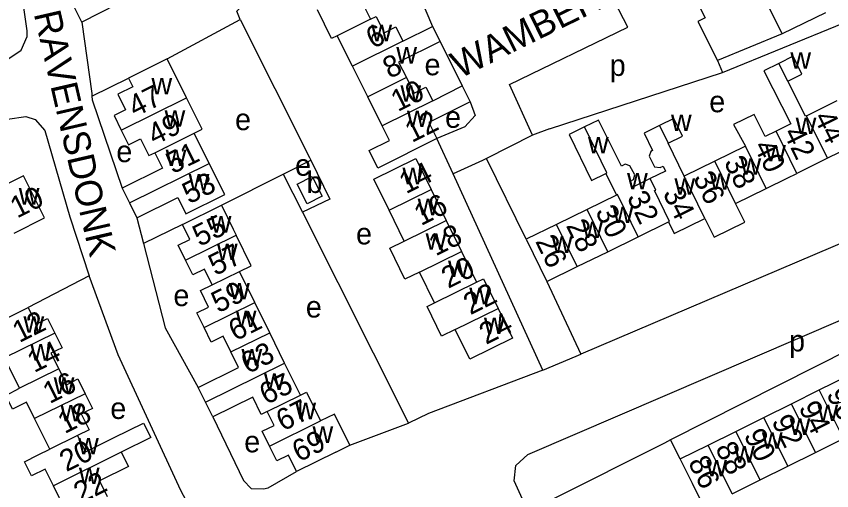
# Model space of a CAD drawing. Extents: x 157794 to 159375, y 380877 to 382306.
# Drawn here: x 158356.3 to 158508.3, y 381547.1 to 381635.5 of the extents above; entities that cross this region are included whole.
import ezdxf

# ---------------------------------------------------------------- set-up
doc = ezdxf.new("R2010")
doc.units = 0
for name, color, linetype in [('BLT_Basislijn', 7, 'Continuous'), ('BLT_Bebouwing', 7, 'Continuous'), ('BLT_Centroide', 7, 'Continuous'), ('BLT_Huisnummer', 7, 'Continuous'), ('BLT_Huisnummer_ tussenligend', 7, 'Continuous'), ('BLT_Onderverdeling_panden', 7, 'Continuous'), ('BLT_Straatnaam', 7, 'Continuous')]:
    doc.layers.add(name, color=color, linetype=linetype)

msp = doc.modelspace()

# ---------------------------------------------------------------- linework, layer by layer
at = {"layer": 'BLT_Basislijn'}
for p, q in [((158426.31, 381651.29), (158433.86, 381633.66)), ((158384.42, 381627.62), (158397.98, 381634.93)), ((158499.08, 381632.26), (158486.99, 381627.33)), ((158435.27, 381630.84), (158439.41, 381622.56)), ((158486.99, 381627.33), (158487.96, 381625.08)), ((158370.34, 381620.66), (158377.17, 381624.03)), ((158455.71, 381614.58), (158487.96, 381625.08)), ((158452.51, 381613.42), (158443.96, 381609.03)), ((158437.69, 381606.18), (158434.68, 381612.75)), ((158406.01, 381606.12), (158411.16, 381608.72)), ((158451.34, 381593.99), (158443.96, 381609.03)), ((158394.51, 381600.34), (158406.01, 381606.12)), ((158406.01, 381606.12), (158409.65, 381599.06)), ((158454.42, 381569.6), (158437.69, 381606.18)), ((158531.99, 381602.59), (158461.52, 381572.61)), ((158378.74, 381598), (158379.99, 381593.18)), ((158409.65, 381599.06), (158429.41, 381559.71)), ((158387.23, 381596.75), (158379.99, 381593.18)), ((158369.82, 381587.16), (158358.45, 381581.26)), ((158455.19, 381586.12), (158461.52, 381572.61)), ((158529.73, 381582.61), (158478.22, 381556.59)), ((158418.46, 381555.63), (158429.41, 381559.71)), ((158480.07, 381553.05), (158478.22, 381556.59))]:
    msp.add_line(p, q, dxfattribs=at)
for points in [[(158333.92, 381618.28), (158353.73, 381626.96), (158357.15, 381629.2), (158358.3, 381631.79), (158358.3, 381632.82), (158354.9, 381656.82)], [(158481.25, 381649.01), (158482.33, 381646.83), (158480.93, 381646.13), (158483.51, 381640.93), (158482.18, 381640.27), (158484.68, 381635.23), (158483.32, 381634.56), (158486.99, 381627.33)], [(158397.98, 381634.93), (158397.4, 381636.52), (158398.36, 381637.43), (158409.44, 381642.68)], [(158452.51, 381613.42), (158448.19, 381622.81), (158470.26, 381633.5), (158466.15, 381641.57)], [(158368.49, 381634.45), (158370.32, 381621.16), (158370.34, 381620.66)], [(158397.98, 381634.93), (158410.91, 381609.24), (158411.16, 381608.72)], [(158487.96, 381625.08), (158510.46, 381634.29), (158511.64, 381634.27), (158512.56, 381632.75), (158513.27, 381633.06), (158513.86, 381632.9), (158516.19, 381633.99)], [(158370.34, 381620.66), (158370.38, 381619.96), (158376.01, 381603.52)], [(158440.89, 381619.61), (158441.82, 381617.04), (158439.9, 381614.93), (158434.68, 381612.75)], [(158318.57, 381599.87), (158354.61, 381616.4), (158358.01, 381616.87), (158359.79, 381616.31), (158361.61, 381614.24), (158366.23, 381598.17), (158369.82, 381587.16)], [(158455.71, 381614.58), (158452.51, 381613.42)], [(158411.16, 381608.72), (158414.72, 381601.49), (158409.65, 381599.06)], [(158443.96, 381609.03), (158443.2, 381608.64), (158437.69, 381606.18)], [(158451.81, 381542.95), (158449.11, 381549.01), (158449.43, 381551.81), (158451.61, 381553.86), (158561.13, 381600.93)], [(158379.99, 381593.18), (158384.04, 381577.49), (158390.19, 381566.38)], [(158379.01, 381534.43), (158389.61, 381538.83), (158389.96, 381539.81), (158389.99, 381541.44), (158386.97, 381547.16), (158375.23, 381572.49), (158369.82, 381587.16)], [(158454.42, 381569.6), (158460.65, 381572.24), (158461.52, 381572.61)], [(158454.42, 381569.6), (158433.11, 381561.51), (158429.41, 381559.71)], [(158392.88, 381560.91), (158398.61, 381549.07), (158400.04, 381547.56), (158402.33, 381547.52), (158403.23, 381547.68), (158408.5, 381550.73)], [(158478.22, 381556.59), (158477.09, 381556.02), (158455.91, 381545.38), (158451.81, 381542.95)]]:
    msp.add_lwpolyline(points, dxfattribs=at)
at = {"layer": 'BLT_Bebouwing'}
for p, q in [((158368.49, 381634.45), (158367.11, 381637.2)), ((158507.17, 381636.16), (158499.08, 381632.26)), ((158428.36, 381630.92), (158433.86, 381633.66)), ((158433.86, 381633.66), (158435.27, 381630.84)), ((158418.94, 381626.23), (158416.1, 381631.92)), ((158384.42, 381627.62), (158377.17, 381624.03)), ((158388.02, 381620.36), (158384.42, 381627.62)), ((158421.78, 381620.53), (158418.94, 381626.23)), ((158433.9, 381619.81), (158439.41, 381622.56)), ((158439.41, 381622.56), (158440.89, 381619.61)), ((158424.48, 381615.12), (158421.78, 381620.53)), ((158503.6, 381617.01), (158509.3, 381619.82)), ((158392.25, 381608.12), (158389.45, 381613.78)), ((158513.2, 381611.88), (158507.49, 381609.08)), ((158492.21, 381611.35), (158486.49, 381608.55)), ((158507.49, 381609.08), (158501.78, 381606.27)), ((158486.49, 381608.55), (158480.78, 381605.74)), ((158376.01, 381603.52), (158377.38, 381600.76)), ((158433.61, 381603.27), (158436.44, 381597.5)), ((158490.35, 381600.67), (158496.07, 381603.47)), ((158468.16, 381602.23), (158462.68, 381599.54)), ((158377.38, 381600.76), (158378.74, 381598)), ((158387.23, 381596.75), (158394.51, 381600.34)), ((158462.68, 381599.54), (158457.01, 381596.76)), ((158428.6, 381593.66), (158425.77, 381599.43)), ((158436.44, 381597.5), (158439.26, 381591.74)), ((158457.01, 381596.76), (158451.34, 381593.99)), ((158472.2, 381594.46), (158477.87, 381597.23)), ((158451.34, 381593.99), (158455.19, 381586.12)), ((158466.53, 381591.68), (158472.2, 381594.46)), ((158439.26, 381591.74), (158442.09, 381585.97)), ((158460.86, 381588.9), (158466.53, 381591.68)), ((158455.19, 381586.12), (158460.86, 381588.9)), ((158400.73, 381582.23), (158397.89, 381588)), ((158434.25, 381582.12), (158431.42, 381587.89)), ((158351.23, 381577.69), (158358.45, 381581.26)), ((158403.52, 381576.58), (158400.73, 381582.23)), ((158406.3, 381570.92), (158403.52, 381576.58)), ((158356.89, 381566.23), (158354.09, 381571.89)), ((158409.24, 381564.96), (158406.3, 381570.92)), ((158505.98, 381565.92), (158511.16, 381568.5)), ((158391.53, 381563.65), (158390.19, 381566.38)), ((158500.8, 381563.35), (158505.98, 381565.92)), ((158392.88, 381560.91), (158391.53, 381563.65)), ((158495.62, 381560.77), (158500.8, 381563.35)), ((158362.49, 381554.87), (158359.68, 381560.57)), ((158490.43, 381558.2), (158495.62, 381560.77)), ((158485.25, 381555.62), (158490.43, 381558.2)), ((158505.3, 381554.29), (158510.48, 381556.87)), ((158480.07, 381553.05), (158485.25, 381555.62)), ((158415.86, 381554.35), (158408.5, 381550.73)), ((158500.11, 381551.72), (158505.3, 381554.29)), ((158494.93, 381549.15), (158500.11, 381551.72)), ((158365.95, 381542.44), (158363.17, 381548.08)), ((158489.75, 381546.57), (158494.93, 381549.15))]:
    msp.add_line(p, q, dxfattribs=at)
for points in [[(158380.39, 381643.8), (158373.74, 381640.47), (158375.1, 381637.77), (158368.49, 381634.45)], [(158421.9, 381641.47), (158423.25, 381638.75), (158421, 381637.63), (158422.3, 381635.01)], [(158499.08, 381632.26), (158495.45, 381639.6), (158495.1, 381640.29), (158497.92, 381641.82)], [(158416.1, 381631.92), (158415.06, 381631.4), (158412.4, 381636.74)], [(158422.3, 381635.01), (158423.33, 381635.52), (158424.86, 381632.46), (158427.04, 381633.55), (158428.36, 381630.92)], [(158435.27, 381630.84), (158427.55, 381627.01), (158428.99, 381624.13)], [(158500.11, 381623.43), (158502.74, 381624.76), (158501.11, 381628.09), (158498.44, 381626.75)], [(158498.44, 381626.75), (158495.65, 381625.36), (158500.7, 381615.5)], [(158377.17, 381624.03), (158377.97, 381622.41), (158375.18, 381621.03), (158376.62, 381618.14), (158374.48, 381617.08), (158375.84, 381614.33)], [(158428.99, 381624.13), (158430.43, 381621.24), (158432.63, 381622.34), (158433.9, 381619.81)], [(158503.6, 381617.01), (158503.39, 381616.91), (158500.11, 381623.43)], [(158389.45, 381613.78), (158390.92, 381614.51), (158388.02, 381620.36)], [(158440.89, 381619.61), (158433.17, 381615.78), (158434.68, 381612.75)], [(158474.42, 381605.3), (158471.19, 381603.71), (158470.66, 381604.74), (158471.33, 381605.1), (158471.57, 381605.98), (158470.66, 381607.7), (158469.78, 381608.01), (158469.08, 381607.64), (158464.83, 381616.21), (158462.22, 381614.93)], [(158477.81, 381611.89), (158480.45, 381613.18), (158478.84, 381616.47), (158476.2, 381615.17)], [(158493.86, 381617.25), (158490.01, 381615.35), (158492.21, 381611.35)], [(158497.92, 381614.14), (158495.87, 381613.17), (158493.86, 381617.25)], [(158434.68, 381612.75), (158423.68, 381607.26), (158422.06, 381610.53), (158425.83, 381612.41), (158424.48, 381615.12)], [(158462.22, 381614.93), (158459.34, 381613.52), (158463.54, 381604.94), (158466.2, 381606.24)], [(158476.2, 381615.17), (158473.3, 381613.75), (158474.88, 381610.53), (158474.55, 381610.37), (158474.28, 381609.48), (158475.25, 381607.49), (158476.31, 381607.36), (158476.86, 381607.63), (158477.31, 381606.71), (158474.42, 381605.3)], [(158500.7, 381615.5), (158497.92, 381614.14)], [(158375.84, 381614.33), (158377.2, 381611.58), (158379.43, 381612.69), (158380.97, 381609.58), (158382.07, 381610.12)], [(158480.78, 381605.74), (158477.81, 381611.89)], [(158382.07, 381610.12), (158383.5, 381607.23), (158376.01, 381603.52)], [(158425.77, 381599.43), (158422.94, 381605.2), (158430.78, 381609.04), (158433.61, 381603.27)], [(158378.74, 381598), (158386.37, 381601.78), (158387.88, 381598.72), (158395.13, 381602.31), (158392.25, 381608.12)], [(158355.87, 381595.11), (158361.54, 381597.96), (158357.58, 381605.84), (158351.91, 381602.99)], [(158466.2, 381606.24), (158468.16, 381602.23)], [(158496.07, 381603.47), (158500, 381605.4), (158501.78, 381606.27)], [(158394.51, 381600.34), (158396.72, 381595.85), (158397.25, 381594.78)], [(158484.64, 381597.88), (158486.39, 381594.36), (158492.07, 381597.15), (158490.35, 381600.67)], [(158387.81, 381590.13), (158386.45, 381592.9), (158388.61, 381593.96), (158387.23, 381596.75)], [(158477.87, 381597.23), (158478.93, 381595.08), (158484.64, 381597.88)], [(158397.89, 381588), (158400.06, 381589.07), (158397.25, 381594.78)], [(158431.42, 381587.89), (158428.73, 381586.57), (158425.9, 381592.34), (158428.6, 381593.66)], [(158392.78, 381585.49), (158391.33, 381588.43), (158389.17, 381587.37), (158387.81, 381590.13)], [(158442.09, 381585.97), (158443.38, 381586.6), (158446.09, 381581.08)], [(158391.27, 381577.57), (158389.93, 381580.3), (158392.11, 381581.37), (158390.61, 381584.42), (158392.78, 381585.49)], [(158358.45, 381581.26), (158359.96, 381578.19), (158362.1, 381579.25), (158363.46, 381576.51)], [(158438.1, 381577.16), (158435.57, 381575.91), (158432.86, 381581.44), (158434.25, 381582.12)], [(158446.09, 381581.08), (158448.8, 381575.55), (158440.8, 381571.64), (158438.1, 381577.16)], [(158396.25, 381573), (158394.81, 381575.92), (158392.61, 381574.84), (158391.27, 381577.57)], [(158363.46, 381576.51), (158364.81, 381573.77), (158362.73, 381572.74), (158364.17, 381569.82)], [(158390.19, 381566.38), (158397.69, 381570.07), (158396.25, 381573)], [(158364.17, 381569.82), (158365.61, 381566.9), (158367.76, 381567.97), (158369.11, 381565.22)], [(158359.68, 381560.57), (158358.17, 381563.63), (158355.56, 381562.32), (158354.3, 381564.88), (158356.89, 381566.23)], [(158369.11, 381565.22), (158370.47, 381562.48), (158368.37, 381561.44), (158369.83, 381558.49), (158367.65, 381557.42)], [(158403.03, 381561.9), (158401.93, 381561.36), (158400.34, 381564.58), (158392.88, 381560.91)], [(158409.24, 381564.96), (158410.36, 381565.51), (158413.01, 381560.14)], [(158403.48, 381555.45), (158402.12, 381558.21), (158404.32, 381559.29), (158403.03, 381561.9)], [(158418.46, 381555.63), (158415.61, 381561.42), (158413.01, 381560.14)], [(158374.51, 381557.05), (158380, 381559.75), (158381.33, 381557.05), (158375.84, 381554.34)], [(158367.65, 381557.42), (158369.14, 381554.4), (158374.51, 381557.05)], [(158408.5, 381550.73), (158407.01, 381553.75), (158404.84, 381552.68), (158403.48, 381555.45)], [(158415.86, 381554.35), (158418.46, 381555.63)], [(158363.17, 381548.08), (158361.65, 381551.17), (158359.1, 381549.91), (158357.79, 381552.55), (158360.34, 381553.81), (158362.49, 381554.87)], [(158375.84, 381554.34), (158377.18, 381551.63), (158371.78, 381548.96), (158373.23, 381546.04)], [(158484.57, 381543.99), (158484.04, 381545.06), (158482.33, 381548.5), (158480.07, 381553.05)]]:
    msp.add_lwpolyline(points, dxfattribs=at)
msp.add_lwpolyline([(158408.65, 381604.28), (158411.44, 381605.67), (158413.27, 381602), (158410.47, 381600.61)], close=True, dxfattribs=at)
at = {"layer": 'BLT_Onderverdeling_panden'}
for p, q in [((158422.3, 381635.01), (158416.1, 381631.92)), ((158428.36, 381630.92), (158418.94, 381626.23)), ((158500.11, 381623.43), (158498.44, 381626.75)), ((158428.99, 381624.13), (158421.78, 381620.53)), ((158375.84, 381614.33), (158388.02, 381620.36)), ((158433.9, 381619.81), (158424.48, 381615.12)), ((158507.49, 381609.08), (158503.6, 381617.01)), ((158476.2, 381615.17), (158477.81, 381611.89)), ((158382.07, 381610.12), (158389.45, 381613.78)), ((158501.78, 381606.27), (158497.92, 381614.14)), ((158496.07, 381603.47), (158492.21, 381611.35)), ((158377.38, 381600.76), (158392.25, 381608.12)), ((158490.35, 381600.67), (158486.49, 381608.55)), ((158484.64, 381597.88), (158480.78, 381605.74)), ((158425.77, 381599.43), (158433.61, 381603.27)), ((158466.53, 381591.68), (158462.68, 381599.54)), ((158428.6, 381593.66), (158436.44, 381597.5)), ((158460.86, 381588.9), (158457.01, 381596.76)), ((158387.81, 381590.13), (158397.25, 381594.78)), ((158431.42, 381587.89), (158439.26, 381591.74)), ((158392.78, 381585.49), (158397.89, 381588)), ((158434.25, 381582.12), (158442.09, 381585.97)), ((158391.27, 381577.57), (158400.73, 381582.23)), ((158438.1, 381577.16), (158446.09, 381581.08)), ((158363.46, 381576.51), (158354.09, 381571.89)), ((158396.25, 381573), (158403.52, 381576.58)), ((158391.53, 381563.65), (158406.3, 381570.92)), ((158364.17, 381569.82), (158356.89, 381566.23)), ((158369.11, 381565.22), (158359.68, 381560.57)), ((158403.03, 381561.9), (158409.24, 381564.96)), ((158510.48, 381556.87), (158505.98, 381565.92)), ((158505.3, 381554.29), (158500.8, 381563.35)), ((158403.48, 381555.45), (158413.01, 381560.14)), ((158500.11, 381551.72), (158495.62, 381560.77)), ((158367.65, 381557.42), (158362.49, 381554.87)), ((158494.93, 381549.15), (158490.43, 381558.2)), ((158489.75, 381546.57), (158485.25, 381555.62)), ((158375.84, 381554.34), (158363.17, 381548.08))]:
    msp.add_line(p, q, dxfattribs=at)
for points in [[(158466.2, 381606.24), (158466.37, 381606.4), (158462.22, 381614.93)], [(158477.87, 381597.23), (158478.07, 381597.33), (158475.28, 381603.05), (158475.48, 381603.15), (158474.42, 381605.3)], [(158472.2, 381594.46), (158468.35, 381602.32), (158468.16, 381602.23)]]:
    msp.add_lwpolyline(points, dxfattribs=at)

# ---------------------------------------------------------------- texts
at = {"layer": 'BLT_Centroide'}
for s, p in [('w', (158422.45, 381630.88)), ('w', (158427.11, 381626.73)), ('w', (158500.59, 381625.77)), ('e', (158432.38, 381624.55)), ('p', (158466.91, 381624.43)), ('w', (158381.46, 381620.97)), ('w', (158427.88, 381619.62)), ('e', (158485.46, 381617.66)), ('w', (158383.91, 381614.97)), ('w', (158429.09, 381614.91)), ('e', (158436.21, 381614.76)), ('e', (158397.05, 381614.33)), ('w', (158478.33, 381614.17)), ('w', (158501.58, 381613.61)), ('w', (158462.86, 381609.98)), ('e', (158374.92, 381608.37)), ('w', (158384.12, 381607.62)), ('w', (158495.89, 381608.5)), ('e', (158408.24, 381605.83)), ('w', (158491.28, 381606)), ('w', (158428.27, 381604.25)), ('w', (158388.39, 381603.06)), ('b', (158410.38, 381602.62)), ('w', (158470.14, 381603.27)), ('w', (158485.56, 381603.22)), ('w', (158478.97, 381602.3)), ('w', (158356.72, 381600.47)), ('w', (158431.1, 381598.47)), ('w', (158467.44, 381597)), ('w', (158392.51, 381595.25)), ('w', (158461.77, 381594.22)), ('e', (158419.61, 381593.04)), ('w', (158432.58, 381592.03)), ('w', (158456.09, 381591.44)), ('w', (158393.67, 381590.12)), ('w', (158436.76, 381586.94)), ('w', (158395.93, 381582.78)), ('e', (158385.56, 381581.54)), ('w', (158440.73, 381581.88)), ('e', (158410.25, 381579.41)), ('w', (158397.18, 381577.62)), ('w', (158357.6, 381576.56)), ('w', (158443.45, 381576.34)), ('p', (158500.35, 381573.09)), ('w', (158358.88, 381571.38)), ('w', (158398.25, 381570.45)), ('w', (158363.23, 381565.19)), ('w', (158402.45, 381565.91)), ('w', (158364.5, 381560.06)), ('e', (158373.79, 381560.51)), ('w', (158408.29, 381560.47)), ('w', (158505.64, 381560.11)), ('w', (158500.45, 381557.53)), ('w', (158411.49, 381556.06)), ('w', (158367.78, 381553.91)), ('e', (158398.76, 381554.29)), ('w', (158495.28, 381554.95)), ('w', (158490.09, 381552.39)), ('w', (158484.91, 381549.8)), ('w', (158367.93, 381548.38))]:
    msp.add_text(s, height=4, dxfattribs=at).set_placement(p)
at = {"layer": 'BLT_Huisnummer'}
for s, rotation, p in [('6', 26.4946, (158422.74, 381629.42)), ('47', 26.3463, (158378.4, 381616.68)), ('10', 26.4946, (158427.39, 381617.68)), ('42', 296.0997, (158499.2, 381613.83)), ('51', 26.3463, (158385.43, 381606.1)), ('38', 296.0997, (158488.13, 381608.36)), ('14', 26.4946, (158428.92, 381602.37)), ('10', 26.6706, (158356.42, 381597.83)), ('34', 296.0997, (158476.73, 381602.58)), ('30', 296.0997, (158464.14, 381599.18)), ('55', 26.3463, (158390.41, 381592.55)), ('18', 26.4946, (158434.44, 381590.79)), ('26', 296.0997, (158452.96, 381593.63)), ('59', 26.3463, (158393.9, 381580.17)), ('12', 26.2747, (158356.81, 381574.64)), ('24', 26.4946, (158443.85, 381574.3)), ('63', 26.3463, (158399.42, 381568.83)), ('16', 26.2747, (158362.48, 381563.27)), ('94', 296.418, (158502.06, 381562.65)), ('90', 296.418, (158491.84, 381557.49)), ('69', 26.3463, (158408.96, 381552.41)), ('20', 26.2747, (158365.58, 381550.58)), ('86', 296.418, (158481.45, 381552.44))]:
    msp.add_text(s, height=4, rotation=rotation, dxfattribs=at).set_placement(p)
at = {"layer": 'BLT_Huisnummer_ tussenligend'}
for s, rotation, p in [('8', 26.4946, (158425.87, 381623.84)), ('12', 26.4946, (158430.03, 381611.94)), ('49', 26.3463, (158382.02, 381611.43)), ('44', 296.0997, (158504.87, 381616.74)), ('40', 296.0997, (158493.67, 381611.37)), ('53', 26.3463, (158388.48, 381600.48)), ('36', 296.0997, (158482.38, 381605.48)), ('16', 26.4946, (158431.72, 381596.45)), ('32', 296.0997, (158470.03, 381601.81)), ('28', 296.0997, (158458.7, 381596.55)), ('57', 26.3463, (158393.36, 381587.12)), ('20', 26.4946, (158436.8, 381584.74)), ('22', 26.4946, (158440.92, 381579.82)), ('61', 26.3463, (158397.1, 381574.95)), ('14', 26.2747, (158359.59, 381569.05)), ('65', 26.3463, (158402.86, 381563.08)), ('96', 296.418, (158507.23, 381565.18)), ('18', 26.2747, (158365.27, 381557.68)), ('67', 26.3463, (158405.97, 381558.15)), ('92', 296.418, (158497.01, 381560.12)), ('88', 296.418, (158486.51, 381555.07)), ('22', 26.2747, (158368.22, 381544.67))]:
    msp.add_text(s, height=4, rotation=rotation, dxfattribs=at).set_placement(p)
at = {"layer": 'BLT_Straatnaam'}
for s, rotation, p in [('WAMBERG', 26.2617, (158438.93, 381623.88)), ('RAVENSDONK', 283.0059, (158359.5, 381636.04))]:
    msp.add_text(s, height=5, rotation=rotation, dxfattribs=at).set_placement(p)

doc.saveas('drawing.dxf')
